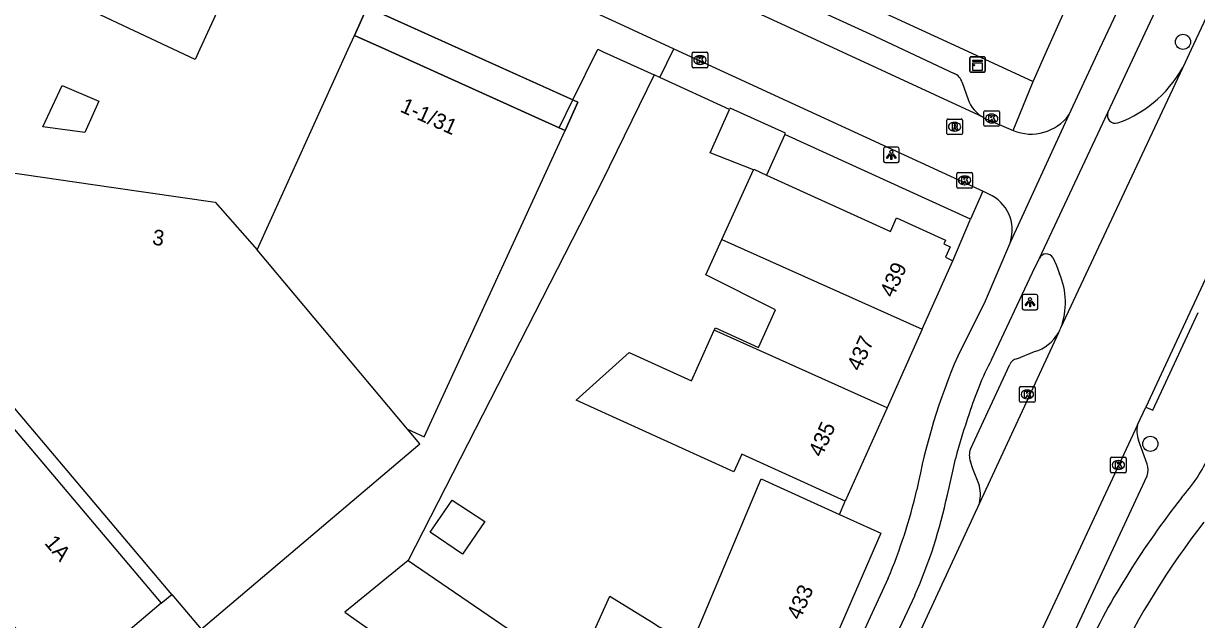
# Model space of a CAD drawing. Extents: x 162990 to 165007, y 383433 to 384336.
# Drawn here: x 163723.1 to 163798.9, y 383963.2 to 384001.7 of the extents above; entities that cross this region are included whole.
import ezdxf

# ---------------------------------------------------------------- set-up
doc = ezdxf.new("R2010")
doc.units = 0
for name, color, linetype in [('IMGEO_Boom', 7, 'Continuous'), ('IMGEO_Fietspad_open', 7, 'Continuous'), ('IMGEO_Kast', 7, 'Continuous'), ('IMGEO_Kolk', 7, 'Continuous'), ('IMGEO_Lichtpunt', 7, 'Continuous'), ('IMGEO_Muur', 7, 'Continuous'), ('IMGEO_Pand', 7, 'Continuous'), ('IMGEO_Pand_nummerreeks', 7, 'Continuous'), ('IMGEO_Pand_overbouw', 7, 'Continuous'), ('IMGEO_Parkeervlak_open', 7, 'Continuous'), ('IMGEO_Rijbaan_lokaal_gesloten', 7, 'Continuous'), ('IMGEO_Rijbaan_lokaal_open', 7, 'Continuous'), ('IMGEO_Rioolput', 7, 'Continuous'), ('IMGEO_Voetpad_open', 7, 'Continuous')]:
    doc.layers.add(name, color=color, linetype=linetype)

msp = doc.modelspace()

# ---------------------------------------------------------------- linework, layer by layer
at = {"layer": 'IMGEO_Boom'}
for centre in [(163798.014, 384000.473), (163795.904, 383974.54)]:
    msp.add_circle(centre, 0.489, dxfattribs=at)
at = {"layer": 'IMGEO_Fietspad_open'}
for points in [[(163816.191, 384049.92), (163792.623, 384000.034), (163790.906, 383996.321), (163790.648, 383995.763)], [(163793.161, 383995.925), (163795.075, 384000), (163817.935, 384048.658)], [(163786.864, 383987.569), (163785.231, 383983.749), (163783.462, 383980.201)], [(163785.638, 383979.969), (163788.303, 383985.587), (163788.717, 383986.483), (163788.738, 383986.527)], [(163782.799, 383971.257), (163783.148, 383972.785), (163783.319, 383973.573)], [(163778.974, 383965.871), (163765.12, 383935.899)], [(163767.045, 383935.06), (163779.029, 383961.201), (163780.705, 383964.772)]]:
    msp.add_lwpolyline(points, dxfattribs=at)
for centre, radius, start, end in [((163821.377, 383963.908), 41.268, 156.74532, 169.30675), ((163806.299, 383969.408), 23.204, 152.92552, 162.273), ((163822.774, 383963.211), 40.793, 161.02747, 165.28425), ((163790.162, 383978.108), 10.478, 317.67724, 335.77207), ((163745.045, 383980.055), 36.775, 337.31303, 346.65225), ((163749.845, 383978.317), 33.701, 336.30204, 347.90753), ((163840.848, 383937.221), 54.666, 141.76521, 154.15504), ((163840.695, 383937.326), 52.376, 142.10337, 154.18448)]:
    msp.add_arc(centre, radius, start, end, dxfattribs=at)
at = {"layer": 'IMGEO_Kast'}
for p, q in [((163784.239, 383998.588), (163784.239, 383999.429)), ((163784.239, 383999.429), (163784.239, 383998.588)), ((163784.314, 383999.513), (163785.155, 383999.513)), ((163785.155, 383999.513), (163784.314, 383999.513)), ((163785.239, 383999.438), (163785.239, 383998.597)), ((163785.239, 383998.597), (163785.239, 383999.438)), ((163785.164, 383998.513), (163784.323, 383998.513)), ((163784.323, 383998.513), (163785.164, 383998.513))]:
    msp.add_line(p, q, dxfattribs=at)
for points in [[(163784.434, 383999.303), (163785.034, 383999.303), (163785.034, 383999.218), (163784.434, 383999.218), (163784.434, 383999.303)], [(163784.434, 383999.128), (163785.034, 383999.128), (163785.034, 383998.639), (163784.434, 383998.639), (163784.434, 383999.128)]]:
    msp.add_lwpolyline(points, dxfattribs=at)
msp.add_circle((163784.518, 383998.977), 0.0377, dxfattribs=at)
for centre, start, end in [((163784.317, 383999.435), 92.4484, 184.28452), ((163784.317, 383999.435), 92.4484, 184.28452), ((163785.161, 383999.435), 2.4484, 94.28452), ((163785.161, 383999.435), 2.4484, 94.28452), ((163784.317, 383998.591), 182.4484, 274.28452), ((163784.317, 383998.591), 182.4484, 274.28452), ((163785.161, 383998.591), 272.4484, 4.28452), ((163785.161, 383998.591), 272.4484, 4.28452)]:
    msp.add_arc(centre, 0.0779, start, end, dxfattribs=at)
at = {"layer": 'IMGEO_Kolk'}
for p, q in [((163766.314, 383998.877), (163766.314, 383999.729)), ((163766.389, 383999.803), (163767.241, 383999.803)), ((163766.802, 383999.583), (163766.827, 383999.583)), ((163767.315, 383999.729), (163767.315, 383998.877)), ((163767.241, 383998.803), (163766.389, 383998.803)), ((163766.825, 383999.023), (163766.8, 383999.023)), ((163785.156, 383995.106), (163785.156, 383995.958)), ((163785.231, 383996.032), (163786.083, 383996.032)), ((163785.644, 383995.812), (163785.669, 383995.812)), ((163786.157, 383995.958), (163786.157, 383995.106)), ((163786.083, 383995.032), (163785.231, 383995.032)), ((163785.667, 383995.252), (163785.642, 383995.252)), ((163783.408, 383991.113), (163783.408, 383991.965)), ((163783.483, 383992.039), (163784.335, 383992.039)), ((163783.896, 383991.819), (163783.921, 383991.819)), ((163784.409, 383991.965), (163784.409, 383991.113)), ((163784.335, 383991.039), (163783.483, 383991.039)), ((163783.919, 383991.259), (163783.894, 383991.259)), ((163787.461, 383977.306), (163787.461, 383978.158)), ((163787.536, 383978.232), (163788.388, 383978.232)), ((163787.949, 383978.012), (163787.974, 383978.012)), ((163788.462, 383978.158), (163788.462, 383977.306)), ((163787.972, 383977.452), (163787.947, 383977.452)), ((163788.388, 383977.232), (163787.536, 383977.232)), ((163793.339, 383972.755), (163793.339, 383973.607)), ((163793.414, 383973.681), (163794.266, 383973.681)), ((163793.827, 383973.461), (163793.852, 383973.461)), ((163794.34, 383973.607), (163794.34, 383972.755)), ((163793.85, 383972.901), (163793.825, 383972.901)), ((163794.266, 383972.681), (163793.414, 383972.681))]:
    msp.add_line(p, q, dxfattribs=at)
for points in [[(163766.314, 383998.877), (163766.314, 383999.729)], [(163766.389, 383999.803), (163767.241, 383999.803)], [(163766.635, 383999.503), (163766.758, 383999.503), (163766.758, 383999.352), (163766.888, 383999.503), (163767.052, 383999.503), (163766.906, 383999.352), (163767.059, 383999.103), (163766.907, 383999.103), (163766.822, 383999.267), (163766.758, 383999.2), (163766.758, 383999.103), (163766.635, 383999.103), (163766.635, 383999.503)], [(163767.315, 383999.729), (163767.315, 383998.877)], [(163767.241, 383998.803), (163766.389, 383998.803)], [(163785.156, 383995.106), (163785.156, 383995.958)], [(163785.231, 383996.032), (163786.083, 383996.032)], [(163785.477, 383995.732), (163785.6, 383995.732), (163785.6, 383995.581), (163785.73, 383995.732), (163785.894, 383995.732), (163785.748, 383995.581), (163785.901, 383995.332), (163785.749, 383995.332), (163785.664, 383995.496), (163785.6, 383995.429), (163785.6, 383995.332), (163785.477, 383995.332), (163785.477, 383995.732)], [(163786.157, 383995.958), (163786.157, 383995.106)], [(163786.083, 383995.032), (163785.231, 383995.032)], [(163783.408, 383991.113), (163783.408, 383991.965)], [(163783.483, 383992.039), (163784.335, 383992.039)], [(163783.729, 383991.739), (163783.852, 383991.739), (163783.852, 383991.588), (163783.982, 383991.739), (163784.146, 383991.739), (163784, 383991.588), (163784.153, 383991.339), (163784.001, 383991.339), (163783.916, 383991.503), (163783.852, 383991.436), (163783.852, 383991.339), (163783.729, 383991.339), (163783.729, 383991.739)], [(163784.409, 383991.965), (163784.409, 383991.113)], [(163784.335, 383991.039), (163783.483, 383991.039)], [(163787.461, 383977.306), (163787.461, 383978.158)], [(163787.536, 383978.232), (163788.388, 383978.232)], [(163788.462, 383978.158), (163788.462, 383977.306)], [(163787.782, 383977.932), (163787.905, 383977.932), (163787.905, 383977.781), (163788.035, 383977.932), (163788.199, 383977.932), (163788.053, 383977.781), (163788.206, 383977.532), (163788.054, 383977.532), (163787.969, 383977.696), (163787.905, 383977.629), (163787.905, 383977.532), (163787.782, 383977.532), (163787.782, 383977.932)], [(163788.388, 383977.232), (163787.536, 383977.232)], [(163793.339, 383972.755), (163793.339, 383973.607)], [(163793.414, 383973.681), (163794.266, 383973.681)], [(163794.34, 383973.607), (163794.34, 383972.755)], [(163793.66, 383973.381), (163793.783, 383973.381), (163793.783, 383973.23), (163793.913, 383973.381), (163794.077, 383973.381), (163793.931, 383973.23), (163794.084, 383972.981), (163793.932, 383972.981), (163793.847, 383973.145), (163793.783, 383973.078), (163793.783, 383972.981), (163793.66, 383972.981), (163793.66, 383973.381)], [(163794.266, 383972.681), (163793.414, 383972.681)]]:
    msp.add_lwpolyline(points, dxfattribs=at)
for centre, start, end in [((163766.391, 383999.727), 91.55205, 178.44795), ((163766.391, 383999.727), 91.55205, 178.44795), ((163767.239, 383999.727), 1.55205, 88.44795), ((163767.239, 383999.727), 1.55205, 88.44795), ((163766.391, 383998.879), 181.55205, 268.44795), ((163766.391, 383998.879), 181.55205, 268.44795), ((163767.239, 383998.879), 271.55205, 358.44795), ((163767.239, 383998.879), 271.55205, 358.44795), ((163785.233, 383995.956), 91.55205, 178.44795), ((163785.233, 383995.956), 91.55205, 178.44795), ((163786.081, 383995.956), 1.55205, 88.44795), ((163786.081, 383995.956), 1.55205, 88.44795), ((163785.233, 383995.108), 181.55205, 268.44795), ((163785.233, 383995.108), 181.55205, 268.44795), ((163786.081, 383995.108), 271.55205, 358.44795), ((163786.081, 383995.108), 271.55205, 358.44795), ((163783.485, 383991.963), 91.55205, 178.44795), ((163783.485, 383991.963), 91.55205, 178.44795), ((163784.333, 383991.963), 1.55205, 88.44795), ((163784.333, 383991.963), 1.55205, 88.44795), ((163783.485, 383991.115), 181.55205, 268.44795), ((163783.485, 383991.115), 181.55205, 268.44795), ((163784.333, 383991.115), 271.55205, 358.44795), ((163784.333, 383991.115), 271.55205, 358.44795), ((163787.538, 383978.156), 91.55205, 178.44795), ((163787.538, 383978.156), 91.55205, 178.44795), ((163788.386, 383978.156), 1.55205, 88.44795), ((163788.386, 383978.156), 1.55205, 88.44795), ((163787.538, 383977.308), 181.55205, 268.44795), ((163787.538, 383977.308), 181.55205, 268.44795), ((163788.386, 383977.308), 271.55205, 358.44795), ((163788.386, 383977.308), 271.55205, 358.44795), ((163793.416, 383973.605), 91.55205, 178.44795), ((163793.416, 383973.605), 91.55205, 178.44795), ((163794.264, 383973.605), 1.55205, 88.44795), ((163794.264, 383973.605), 1.55205, 88.44795), ((163793.416, 383972.757), 181.55205, 268.44795), ((163793.416, 383972.757), 181.55205, 268.44795), ((163794.264, 383972.757), 271.55205, 358.44795), ((163794.264, 383972.757), 271.55205, 358.44795)]:
    msp.add_arc(centre, 0.0765, start, end, dxfattribs=at)
for centre, major_axis, ratio, start_param, end_param in [((163766.801, 383999.303), (-0.387, 0.002), 0.722429, 4.712389, 7.853982), ((163766.826, 383999.303), (-0.39, 0.002), 0.717154, 1.570796, 4.712389), ((163785.643, 383995.532), (-0.387, 0.002), 0.722429, 4.712389, 7.853982), ((163785.668, 383995.532), (-0.39, 0.002), 0.717154, 1.570796, 4.712389), ((163783.895, 383991.539), (-0.387, 0.002), 0.722429, 4.712389, 7.853982), ((163783.92, 383991.539), (-0.39, 0.002), 0.717154, 1.570796, 4.712389), ((163787.948, 383977.732), (-0.387, 0.002), 0.722429, 4.712389, 7.853982), ((163787.973, 383977.732), (-0.39, 0.002), 0.717154, 1.570796, 4.712389), ((163793.826, 383973.181), (-0.387, 0.002), 0.722429, 4.712389, 7.853982), ((163793.851, 383973.181), (-0.39, 0.002), 0.717154, 1.570796, 4.712389)]:
    msp.add_ellipse(centre, major_axis=major_axis, ratio=ratio, start_param=start_param, end_param=end_param, dxfattribs=at)
at = {"layer": 'IMGEO_Lichtpunt'}
for p, q in [((163778.677, 383993.584), (163778.677, 383992.777)), ((163778.677, 383993.584), (163778.677, 383992.777)), ((163779.579, 383993.679), (163778.771, 383993.679)), ((163779.579, 383993.679), (163778.771, 383993.679)), ((163779.673, 383992.777), (163779.673, 383993.584)), ((163779.673, 383992.777), (163779.673, 383993.584)), ((163778.771, 383992.683), (163779.579, 383992.683)), ((163778.771, 383992.683), (163779.579, 383992.683)), ((163787.636, 383984.08), (163787.636, 383983.273)), ((163787.636, 383984.08), (163787.636, 383983.273)), ((163788.538, 383984.175), (163787.73, 383984.175)), ((163788.538, 383984.175), (163787.73, 383984.175)), ((163788.632, 383983.273), (163788.632, 383984.08)), ((163788.632, 383983.273), (163788.632, 383984.08)), ((163787.73, 383983.179), (163788.538, 383983.179)), ((163787.73, 383983.179), (163788.538, 383983.179))]:
    msp.add_line(p, q, dxfattribs=at)
for points in [[(163779.051, 383993.248), (163779.09, 383993.22), (163778.902, 383992.958), (163778.864, 383992.985), (163779.051, 383993.248)], [(163779.153, 383993.2), (163779.2, 383993.2), (163779.2, 383992.878), (163779.153, 383992.878), (163779.153, 383993.2)], [(163779.263, 383993.22), (163779.301, 383993.247), (163779.488, 383992.985), (163779.449, 383992.957), (163779.263, 383993.22)], [(163788.01, 383983.744), (163788.049, 383983.716), (163787.861, 383983.454), (163787.823, 383983.481), (163788.01, 383983.744)], [(163788.112, 383983.696), (163788.159, 383983.696), (163788.159, 383983.374), (163788.112, 383983.374), (163788.112, 383983.696)], [(163788.222, 383983.716), (163788.26, 383983.743), (163788.447, 383983.481), (163788.408, 383983.453), (163788.222, 383983.716)]]:
    msp.add_lwpolyline(points, dxfattribs=at)
for centre in [(163779.176, 383993.382), (163788.135, 383983.878)]:
    msp.add_circle(centre, 0.0994, dxfattribs=at)
for centre, start, end in [((163778.771, 383993.584), 90, 180), ((163778.771, 383993.584), 90, 180), ((163779.579, 383993.584), 0, 90), ((163779.579, 383993.584), 0, 90), ((163778.771, 383992.777), 180, 270), ((163778.771, 383992.777), 180, 270), ((163779.579, 383992.777), 270, 0), ((163779.579, 383992.777), 270, 360), ((163787.73, 383984.08), 90, 180), ((163787.73, 383984.08), 90, 180), ((163788.538, 383984.08), 0, 90), ((163788.538, 383984.08), 0, 90), ((163787.73, 383983.273), 180, 270), ((163787.73, 383983.273), 180, 270), ((163788.538, 383983.273), 270, 0), ((163788.538, 383983.273), 270, 360)]:
    msp.add_arc(centre, 0.0946, start, end, dxfattribs=at)
at = {"layer": 'IMGEO_Muur'}
for points in [[(163757.728, 383994.932), (163758.61, 383996.728)], [(163758.61, 383996.728), (163758.925, 383996.586), (163758.103, 383994.763)]]:
    msp.add_lwpolyline(points, dxfattribs=at)
at = {"layer": 'IMGEO_Pand'}
for points in [[(163731.33, 384010.26), (163737.86, 384007.247), (163735.765, 384002.708), (163734.515, 384000), (163734.207, 383999.334), (163732.785, 384000), (163727.744, 384002.36)], [(163738.208, 383987.065), (163744.1, 384000), (163744.506, 384000.893)], [(163757.728, 383994.932), (163746.487, 384000), (163744.506, 384000.893)], [(163701.43, 383997.012), (163703.909, 383997.461), (163732.007, 383964.256)], [(163725.615, 383997.66), (163727.981, 383996.649), (163727.092, 383994.631), (163724.365, 383994.985), (163725.615, 383997.66)], [(163772.287, 383994.498), (163772.331, 383994.595), (163768.769, 383996.194), (163768.734, 383996.117)], [(163770.27, 383992.215), (163767.48, 383993.323), (163768.734, 383996.117)], [(163747.916, 383975.496), (163748.993, 383974.998), (163756.011, 383990.223), (163758.103, 383994.763)], [(163758.103, 383994.763), (163757.728, 383994.932)], [(163772.287, 383994.498), (163771.112, 383991.88)], [(163732.705, 383964.822), (163718.113, 383982.065), (163714.771, 383986.014), (163721.979, 383992.083), (163728.787, 383991.097), (163735.501, 383990.125), (163738.208, 383987.065)], [(163768.234, 383987.732), (163770.27, 383992.215)], [(163770.27, 383992.215), (163770.288, 383992.254), (163771.112, 383991.88)], [(163771.112, 383991.88), (163779.113, 383988.246), (163779.514, 383989.128), (163782.677, 383987.691), (163782.568, 383987.451), (163782.981, 383987.263), (163782.669, 383986.576), (163783.15, 383986.357)], [(163732.007, 383964.256), (163725.748, 383958.959), (163701.884, 383987.16)], [(163767.739, 383981.869), (163767.811, 383982.026), (163770.596, 383980.761), (163771.696, 383983.182), (163767.195, 383985.445), (163768.234, 383987.732)], [(163768.234, 383987.732), (163781.168, 383981.934)], [(163747.916, 383975.496), (163738.208, 383987.065)], [(163781.168, 383981.934), (163783.15, 383986.357)], [(163776.199, 383970.846), (163771.647, 383972.913), (163769.51, 383973.884), (163768.993, 383972.746), (163758.821, 383977.366), (163762.243, 383980.438), (163766.261, 383978.614), (163767.739, 383981.869)], [(163778.898, 383976.868), (163767.739, 383981.869)], [(163781.168, 383981.934), (163778.898, 383976.868)], [(163778.898, 383976.868), (163776.199, 383970.846)], [(163732.705, 383964.822), (163734.592, 383962.592), (163748.593, 383974.44), (163748.715, 383974.543), (163747.916, 383975.496)], [(163766.33, 383961.758), (163770.764, 383972.292), (163773.937, 383970.851), (163775.823, 383969.994)], [(163751.473, 383967.422), (163749.385, 383968.841), (163750.802, 383970.917), (163752.914, 383969.534), (163751.473, 383967.422)], [(163775.823, 383969.994), (163778.489, 383968.784), (163773.803, 383957.985), (163771.122, 383959.203)], [(163747.968, 383967.015), (163743.883, 383963.686), (163748.025, 383960.761), (163748.93, 383960.122)], [(163747.968, 383967.015), (163758.714, 383959.683), (163758.795, 383959.861)], [(163758.795, 383959.861), (163760.997, 383964.709), (163763.678, 383963.052), (163764.179, 383962.735), (163766.33, 383961.758)]]:
    msp.add_lwpolyline(points, dxfattribs=at)
at = {"layer": 'IMGEO_Pand_overbouw'}
msp.add_lwpolyline([(163758.103, 383994.763), (163758.925, 383996.586), (163745.328, 384002.716), (163744.506, 384000.893), (163746.487, 384000), (163757.728, 383994.932)], close=True, dxfattribs=at)
at = {"layer": 'IMGEO_Parkeervlak_open'}
for points in [[(163787.277, 383980.036), (163788.419, 383980.491)], [(163784.282, 383974.204), (163786.823, 383979.657)], [(163795.692, 383973.241), (163795.134, 383974.785)], [(163784.819, 383971.972), (163784.445, 383972.922), (163784.286, 383973.405)], [(163787.818, 383956.849), (163788.315, 383956.621), (163795.697, 383972.489)]]:
    msp.add_lwpolyline(points, dxfattribs=at)
for centre, radius, start, end in [((163787.694, 383983.011), 2.622, 286.05272, 330.1768), ((163787.498, 383979.309), 0.76, 106.94306, 152.76732), ((163796.893, 383975.377), 1.856, 167.80037, 198.59799), ((163785.353, 383973.81), 1.141, 159.79429, 200.77938), ((163794.631, 383972.858), 1.128, 340.91393, 19.84798), ((163782.745, 383971.277), 2.187, 345.31095, 18.53788)]:
    msp.add_arc(centre, radius, start, end, dxfattribs=at)
at = {"layer": 'IMGEO_Rijbaan_lokaal_gesloten'}
for points in [[(163798.17, 383999.161), (163798.56, 384000), (163800.841, 384004.887)], [(163790.125, 383982.027), (163798.17, 383999.161)], [(163804.546, 383996.107), (163795.615, 383976.916)], [(163789.969, 383981.707), (163784.861, 383970.722)], [(163795.079, 383975.769), (163795.615, 383976.916)], [(163795.079, 383975.769), (163789.902, 383964.696), (163786.656, 383957.76), (163776.508, 383936.015), (163770.272, 383921.927), (163766.204, 383912.135), (163758.54, 383893.202)], [(163784.861, 383970.722), (163780.95, 383962.264), (163773.933, 383946.885)]]:
    msp.add_lwpolyline(points, dxfattribs=at)
msp.add_arc((163787.598, 383983.061), 2.73, 330.27239, 337.74914, dxfattribs=at)
at = {"layer": 'IMGEO_Rijbaan_lokaal_open'}
for points in [[(163785.106, 383995.608), (163772.619, 384001.386), (163765.453, 384004.682), (163756.25, 384008.884), (163740.479, 384016.171), (163739.626, 384016.621), (163739.064, 384016.942), (163738.764, 384017.195)], [(163738.959, 384012.046), (163743.702, 384009.854), (163761.651, 384001.631), (163765.138, 384000.027)], [(163765.138, 384000.027), (163784.879, 383990.947), (163785.085, 383990.846)], [(163785.278, 383995.52), (163787.048, 383994.75)], [(163790.648, 383995.763), (163786.864, 383987.569)], [(163788.738, 383986.527), (163793.161, 383995.925)], [(163785.482, 383990.651), (163785.085, 383990.846)], [(163789.601, 383986.562), (163789.838, 383986.058), (163790.032, 383985.52)], [(163795.615, 383976.916), (163796.068, 383976.706), (163799.003, 383983.013)]]:
    msp.add_lwpolyline(points, dxfattribs=at)
for centre, radius, start, end in [((163791.112, 384002.632), 7.865, 290.05083, 333.8088), ((163786.142, 383997.421), 2.088, 240.25257, 245.55633), ((163788.194, 383997.58), 3.053, 247.95008, 323.48194), ((163793.656, 383995.748), 0.526, 160.28942, 286.86577), ((163784.447, 383988.336), 2.536, 342.39237, 65.91152), ((163789.18, 383986.292), 0.5, 32.63496, 152.00989), ((163785.802, 383983.66), 4.621, 339.30975, 23.7405)]:
    msp.add_arc(centre, radius, start, end, dxfattribs=at)
at = {"layer": 'IMGEO_Rioolput'}
for p, q in [((163782.764, 383994.573), (163782.764, 383995.425)), ((163782.839, 383995.499), (163783.691, 383995.499)), ((163783.765, 383995.425), (163783.765, 383994.573)), ((163783.275, 383994.719), (163783.25, 383994.719)), ((163783.252, 383995.279), (163783.277, 383995.279)), ((163783.691, 383994.499), (163782.839, 383994.499))]:
    msp.add_line(p, q, dxfattribs=at)
for points in [[(163782.764, 383994.573), (163782.764, 383995.425)], [(163782.839, 383995.499), (163783.691, 383995.499)], [(163783.765, 383995.425), (163783.765, 383994.573)], [(163783.353, 383995.197), (163783.101, 383995.199), (163783.101, 383994.799)], [(163783.101, 383994.799), (163783.225, 383994.799), (163783.225, 383994.961), (163783.236, 383994.961)], [(163783.279, 383995.118), (163783.225, 383995.118), (163783.225, 383995.037)], [(163783.225, 383995.037), (163783.277, 383995.037)], [(163783.283, 383994.932), (163783.354, 383994.799), (163783.494, 383994.799), (163783.429, 383994.925)], [(163783.691, 383994.499), (163782.839, 383994.499)]]:
    msp.add_lwpolyline(points, dxfattribs=at)
for centre, radius, start, end in [((163782.841, 383995.423), 0.0765, 91.55205, 178.44795), ((163782.841, 383995.423), 0.0765, 91.55205, 178.44795), ((163783.689, 383995.423), 0.0765, 1.55205, 88.44795), ((163783.689, 383995.423), 0.0765, 1.55205, 88.44795), ((163783.235, 383994.908), 0.0533, 26.02933, 88.69889), ((163783.261, 383995.226), 0.19, 274.7715, 282.96867), ((163783.285, 383995.022), 0.0964, 77.00612, 93.18647), ((163783.299, 383995.079), 0.0378, 276.66336, 79.67722), ((163783.352, 383995.087), 0.109, 350.36119, 89.41601), ((163783.35, 383995.087), 0.112, 277.58423, 350.98172), ((163783.334, 383994.872), 0.108, 29.51342, 73.79051), ((163782.841, 383994.575), 0.0765, 181.55205, 268.44795), ((163782.841, 383994.575), 0.0765, 181.55205, 268.44795), ((163783.689, 383994.575), 0.0765, 271.55205, 358.44795), ((163783.689, 383994.575), 0.0765, 271.55205, 358.44795)]:
    msp.add_arc(centre, radius, start, end, dxfattribs=at)
for centre, major_axis, ratio, start_param, end_param in [((163783.251, 383994.999), (-0.387, 0.002), 0.722429, 4.712389, 7.853982), ((163783.276, 383994.999), (-0.39, 0.002), 0.717154, 1.570796, 4.712389)]:
    msp.add_ellipse(centre, major_axis=major_axis, ratio=ratio, start_param=start_param, end_param=end_param, dxfattribs=at)
at = {"layer": 'IMGEO_Voetpad_open'}
for points in [[(163788.336, 383997.923), (163789.265, 384000), (163796.988, 384017.276), (163804.861, 384033.884), (163809.104, 384042.631), (163809.212, 384042.588), (163810.741, 384045.3), (163810.967, 384045.208), (163817.775, 384059.146), (163818.285, 384059.918)], [(163755.974, 384012.834), (163758.718, 384011.563), (163783.826, 384000), (163788.336, 383997.923)], [(163755.271, 384011.307), (163757.622, 384010.233), (163765.895, 384006.438), (163777.796, 384000.987), (163783.229, 383998.443)], [(163744.506, 384000.893), (163745.328, 384002.716)], [(163745.328, 384002.716), (163758.61, 383996.728)], [(163758.61, 383996.728), (163760.215, 384000), (163760.564, 383999.841), (163763.85, 383998.343)], [(163764.221, 383998.174), (163765.138, 384000.027)], [(163763.85, 383998.343), (163760.473, 383991.442), (163747.968, 383967.015)], [(163764.221, 383998.174), (163763.85, 383998.343)], [(163768.734, 383996.117), (163764.221, 383998.174)], [(163783.759, 383997.852), (163784.138, 383996.766)], [(163787.048, 383994.75), (163788.336, 383997.923)], [(163784.282, 383989.032), (163772.287, 383994.498)], [(163785.085, 383990.846), (163784.282, 383989.032)], [(163783.15, 383986.357), (163784.282, 383989.032)], [(163775.823, 383969.994), (163776.199, 383970.846)], [(163732.007, 383964.256), (163732.705, 383964.822)]]:
    msp.add_lwpolyline(points, dxfattribs=at)
for centre, radius, start, end in [((163782.83, 383997.552), 0.976, 17.88416, 65.8864), ((163786.169, 383997.48), 2.153, 199.37365, 240.41247)]:
    msp.add_arc(centre, radius, start, end, dxfattribs=at)

# ---------------------------------------------------------------- texts
at = {"layer": 'IMGEO_Pand_nummerreeks'}
for s, rotation, p in [('1-1/31', 335.73524, (163747.384, 383995.998)), ('3', 351.76087, (163731.401, 383987.404)), ('439', 65.8615, (163779.296, 383983.919)), ('437', 65.86125, (163777.17, 383979.174)), ('435', 65.86125, (163774.685, 383973.63)), ('1A', 310.23862, (163724.434, 383968.127)), ('433', 66.54258, (163773.286, 383963.123))]:
    msp.add_text(s, height=1, rotation=rotation, dxfattribs=at).set_placement(p)

doc.saveas('drawing.dxf')
